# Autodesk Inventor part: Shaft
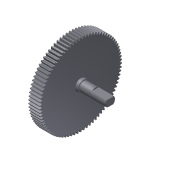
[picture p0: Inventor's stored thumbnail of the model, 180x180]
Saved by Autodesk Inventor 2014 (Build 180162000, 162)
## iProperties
Created: 2010-12
Part Number: Shaft
Material: Steel
Document SubType Name: Modeling
Designer: Thom Tremblay
Density: 1 g/cm^3
Appearance: Steel
CustomPartVersion: 1
Author: Thom Tremblay
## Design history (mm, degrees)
sketch "Main Sketch"
  geometry: L1 (0, 0)-(43, 0) reference; L2 (0, 0)-(0, 45); L3 (12, 45)-(12, 6); L4 (0, 45)-(12, 45); L5 (15, 6)-(15, 5); L6 (12, 6)-(15, 6); L7 (43, 5)-(43, 0); L8 (15, 5)-(43, 5)
  constraints: 16 end point, 4 vertical, 2 horizontal
  dimensions: "d3" = 90 diameter of L4 L1 (derived); "d4" = 12 diameter of L6 L1 (derived); "d5" = 10 diameter of L8 L1 (derived)
revolve "Revolution1" sketch "Main Sketch" stored, may be unused: angle "d6" = 0 deg
node "Retaining Ring Groove1"
chamfer "Chamfer1" distance "d7" = 0.5; stored, may be unused: second distance "d8" = 0.125, angle "d9" = 45 deg
chamfer "Chamfer2" distance "d10" = 0.5; stored, may be unused: second distance "d11" = 0.125, angle "d12" = 45 deg
node "Spur Gear Teeth1"
sketch "Sketch3"
  geometry: L1 (-3.5, 3.571)-(-3.5, -3.571); L2 (3.5, 3.571)-(3.5, -3.571); A1 r 5 centre (0, 0) between (-3.5, 3.571) and (-3.5, -3.571) reference; 1 further point
  constraints: 4 end point, 4 point on circle, 2 parallel, 1 vertical
  dimensions: "d13" = 7 distance between parallel lines of L2 L1
extrude "Extrusion1" cut sketch "Sketch3" distance "d14" = 16; taper "d15" = 0 deg
node "Hole2"
body "Solid1"
feature "Spur Gear2"
feature "iFeature27:1"
sketch "Sketch4"
  geometry: 1 further point
hole "Hole1" sketch "Sketch4" diameter "d16" = 3.242; stored, may be unused: countersink angle "d20" = 90 deg, drill point angle "d22" = 120 deg; dims "d17" = 8, "d18" = 4, "d19" = 2, "d21" = 10
other parameters: "d0" = 0, "d1" = 0, "d2" = 0
